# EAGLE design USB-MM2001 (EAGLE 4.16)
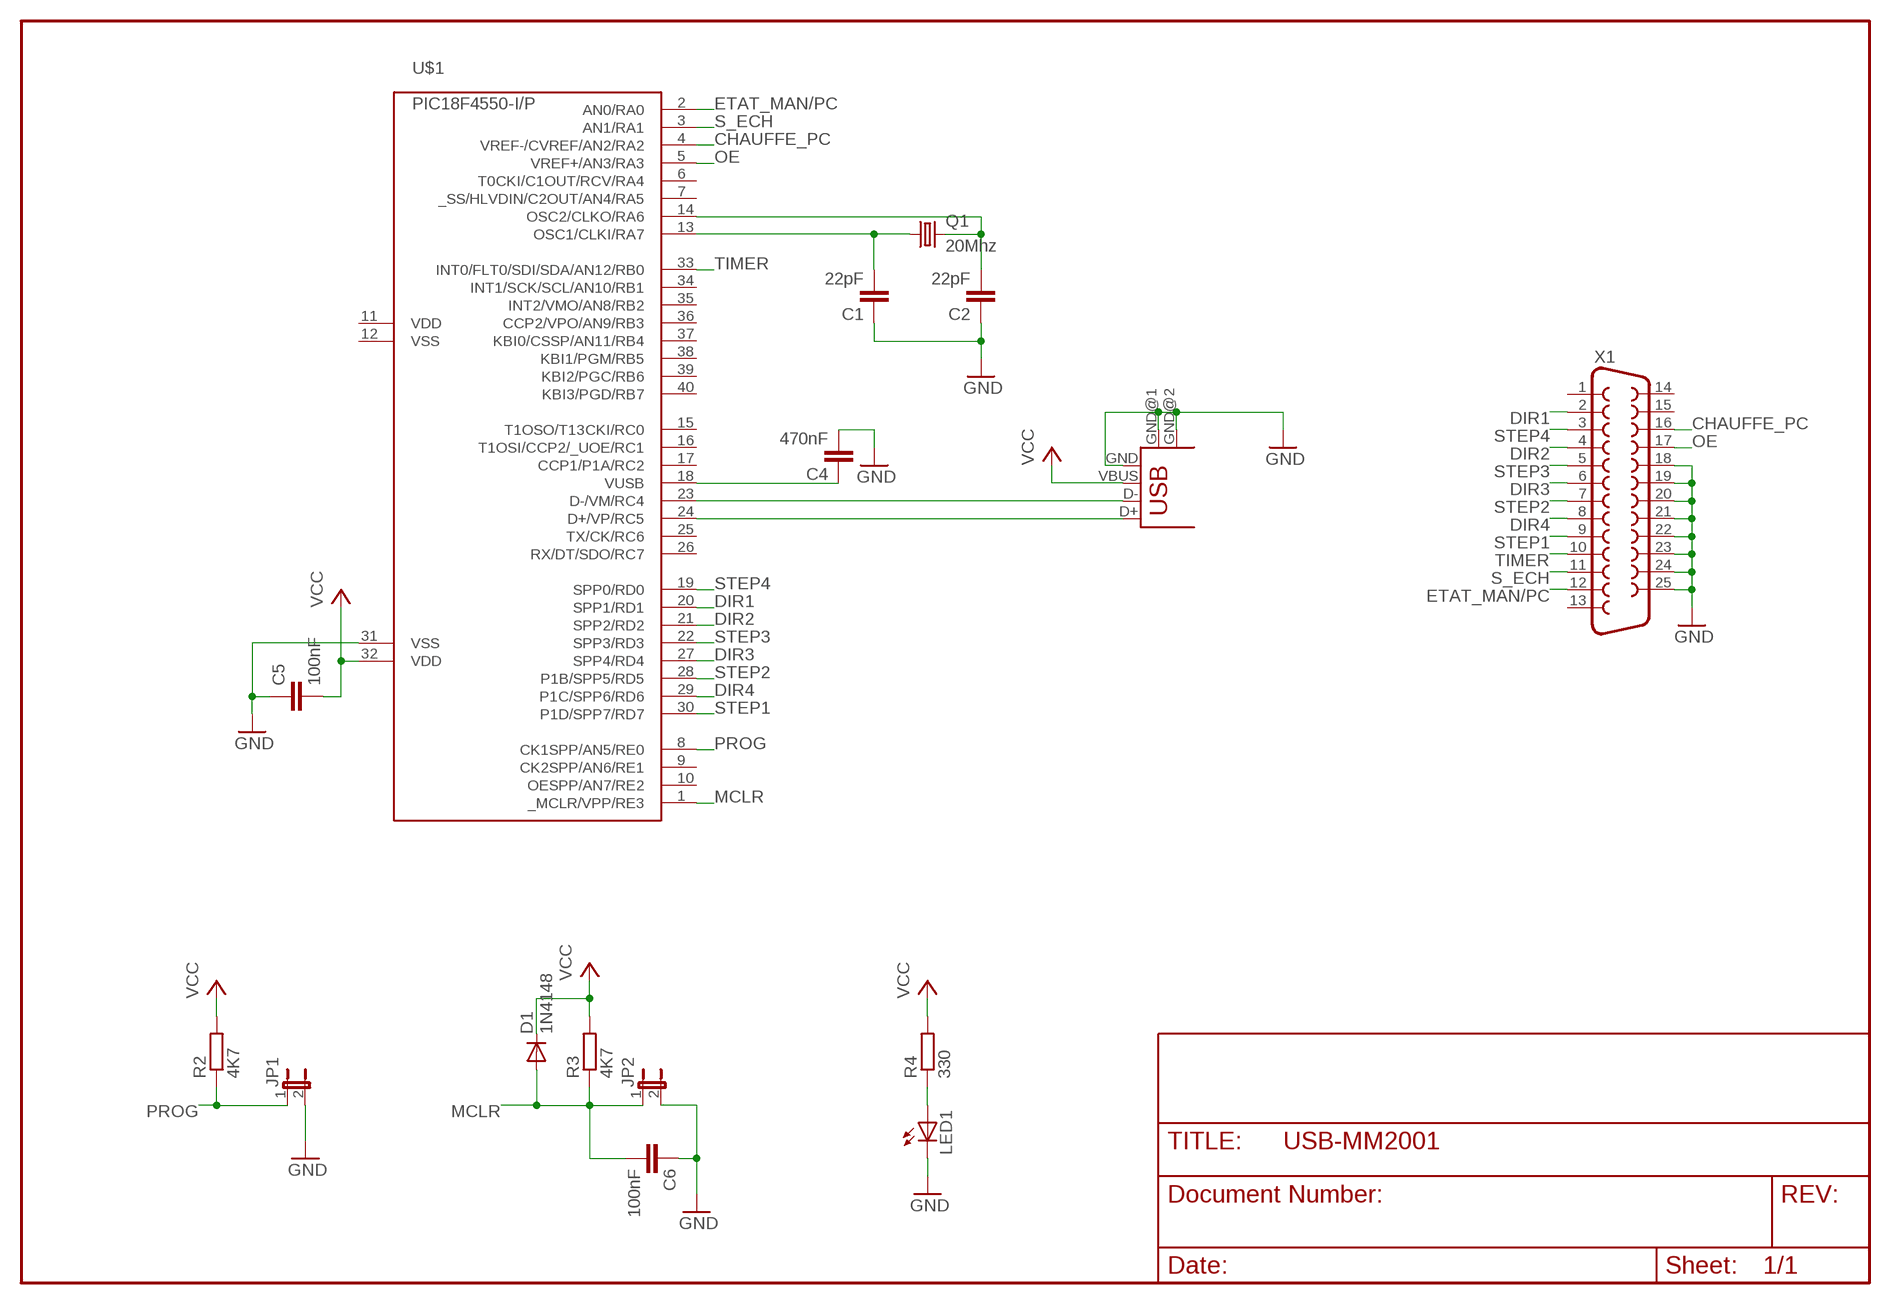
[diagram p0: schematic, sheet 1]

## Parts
C1  22pF  C-EU025-024X044  [C025-024X044]
C2  22pF  C-EU025-024X044  [C025-024X044]
C4  470nF  C-EU025-024X044  [C025-024X044]
C5  100nF  C-EU025-024X044  [C025-024X044]
C6  100nF  C-EU025-024X044  [C025-024X044]
D1  1N4148  [DO35-10]
JP1  JP1E  [JP1]
JP2  JP1E  [JP1]
LED1  LED5MM  [LED5MM]
Q1  20Mhz  CRYTALHC49U-V  [HC49U-V]
R2  4K7  R-EU_0207/10  [0207/10]
R3  4K7  R-EU_0207/10  [0207/10]
R4  330  R-EU_0207/10  [0207/10]
U$1  PIC18F4550-I/P  [DIL40]
USB1  USB-B-H  [USB-B-H]
X1  F25H  [F25H]

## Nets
CHAUFFE_PC: U$1.4(VREF-/CVREF/AN2/RA2) X1.16
DIR1: U$1.20(SPP1/RD1) X1.2
DIR2: U$1.21(SPP2/RD2) X1.4
DIR3: U$1.27(SPP4/RD4) X1.6
DIR4: U$1.29(P1C/SPP6/RD6) X1.8
ETAT_MAN/PC: U$1.2(AN0/RA0) X1.12
GND: C1.1 C2.1 C4.2 C5.1 C6.1 JP1.2 JP2.2 LED1.K(C) U$1.31(VSS) USB1.GND USB1.GND@1(GND) USB1.GND@2(GND) X1.18 X1.19 X1.20 X1.21 X1.22 X1.23 X1.24 X1.25
MCLR: C6.2 D1.A JP2.1 R3.1 U$1.1(_MCLR/VPP/RE3)
N$1: U$1.24(D+/VP/RC5) USB1.D+
N$2: U$1.23(D-/VM/RC4) USB1.D-
N$3: C4.1 U$1.18(VUSB)
N$7: LED1.A R4.1
N$11: C2.2 Q1.2 U$1.14(OSC2/CLKO/RA6)
N$14: C1.2 Q1.1 U$1.13(OSC1/CLKI/RA7)
OE: U$1.5(VREF+/AN3/RA3) X1.17
PROG: JP1.1 R2.1 U$1.8(CK1SPP/AN5/RE0)
S_ECH: U$1.3(AN1/RA1) X1.11
STEP1: U$1.30(P1D/SPP7/RD7) X1.9
STEP2: U$1.28(P1B/SPP5/RD5) X1.7
STEP3: U$1.22(SPP3/RD3) X1.5
STEP4: U$1.19(SPP0/RD0) X1.3
TIMER: U$1.33(INT0/FLT0/SDI/SDA/AN12/RB0) X1.10
VCC: C5.2 D1.C R2.2 R3.2 R4.2 U$1.32(VDD) USB1.VBUS
Unconnected: U$1.6(T0CKI/C1OUT/RCV/RA4) U$1.7(_SS/HLVDIN/C2OUT/AN4/RA5) U$1.9(CK2SPP/AN6/RE1) U$1.10(OESPP/AN7/RE2) U$1.15(T1OSO/T13CKI/RC0) U$1.16(T1OSI/CCP2/_UOE/RC1) U$1.17(CCP1/P1A/RC2) U$1.25(TX/CK/RC6) U$1.26(RX/DT/SDO/RC7) U$1.34(INT1/SCK/SCL/AN10/RB1) U$1.35(INT2/VMO/AN8/RB2) U$1.36(CCP2/VPO/AN9/RB3) U$1.37(KBI0/CSSP/AN11/RB4) U$1.38(KBI1/PGM/RB5) U$1.39(KBI2/PGC/RB6) U$1.40(KBI3/PGD/RB7) X1.1 X1.13 X1.14 X1.15

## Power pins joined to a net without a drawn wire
VDD: U$1.11(VDD)
VSS: U$1.12(VSS)

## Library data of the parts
C1 C2 C4-C6 = rcl:C-EU: CAPACITOR, European symbol
D1 = diode:1N4148: DIODE
JP1 JP2 = jumper:JP1E: JUMPER
LED1 = led:LED: LED
Q1 = crystal:CRYTAL: CRYSTAL
R2-R4 = rcl:R-EU_: RESISTOR, European symbol
U$1 = microchip-pic18fxx5x:PIC18*4550: PIC18*4550 Microchip FLASH Microcontroller with FS-USB DEVICE FEATURES FeaturePIC18*4550 Program Memory (bytes) 32k Program Memory (instructions) 16384 I/O Ports Ports A, B, C, D, E Capture/Compare/PWM Modules 1 Enhanced Capture/Compare/PWM Modules 1 Parallel Communications (PSP) Yes 10-bit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
USB1 = con-usb-2:USB: USB Connectors
X1 = con-subd:F25: SUB-D

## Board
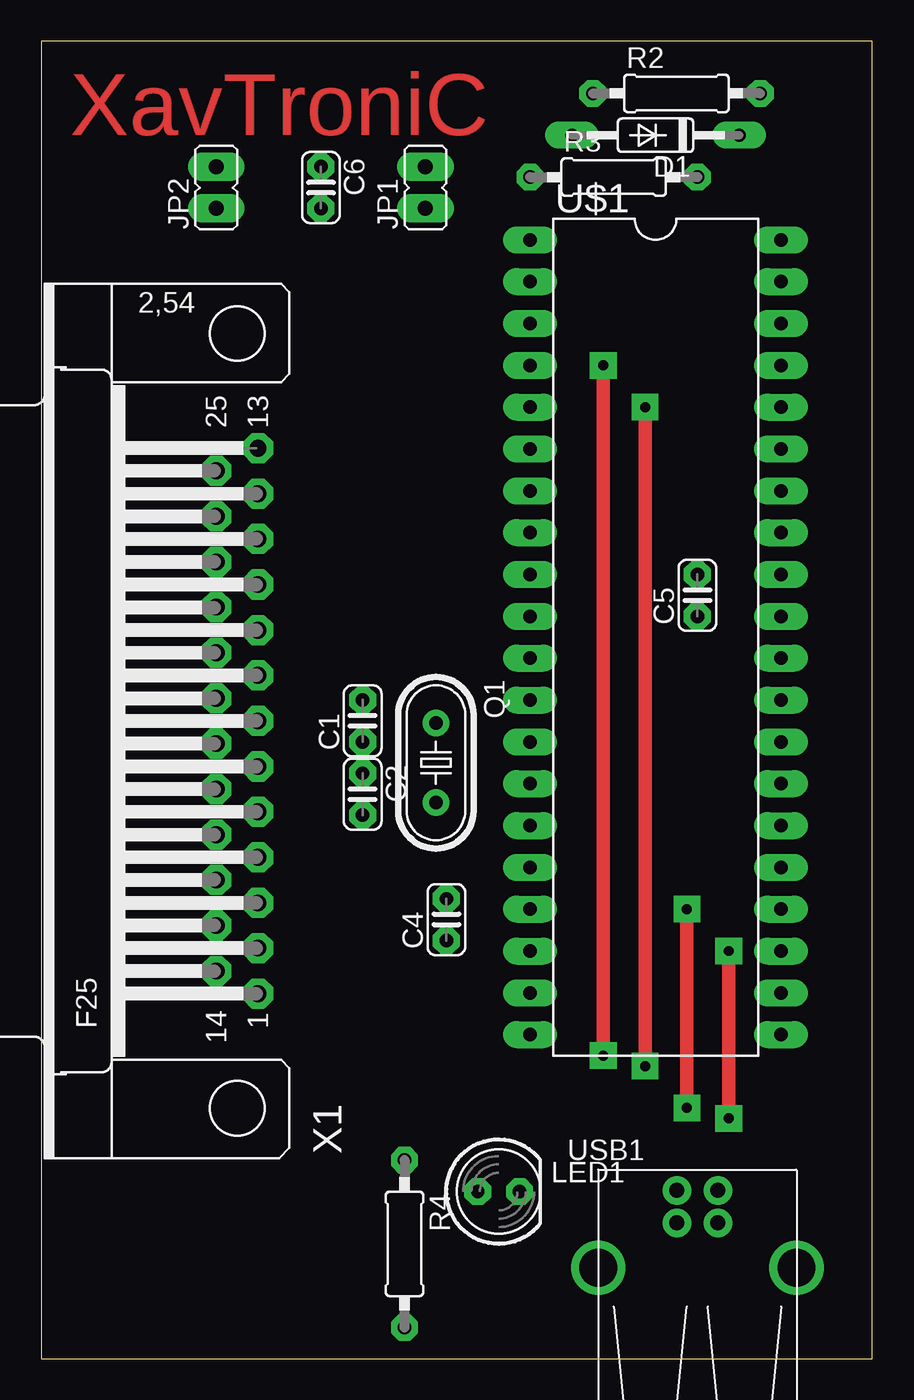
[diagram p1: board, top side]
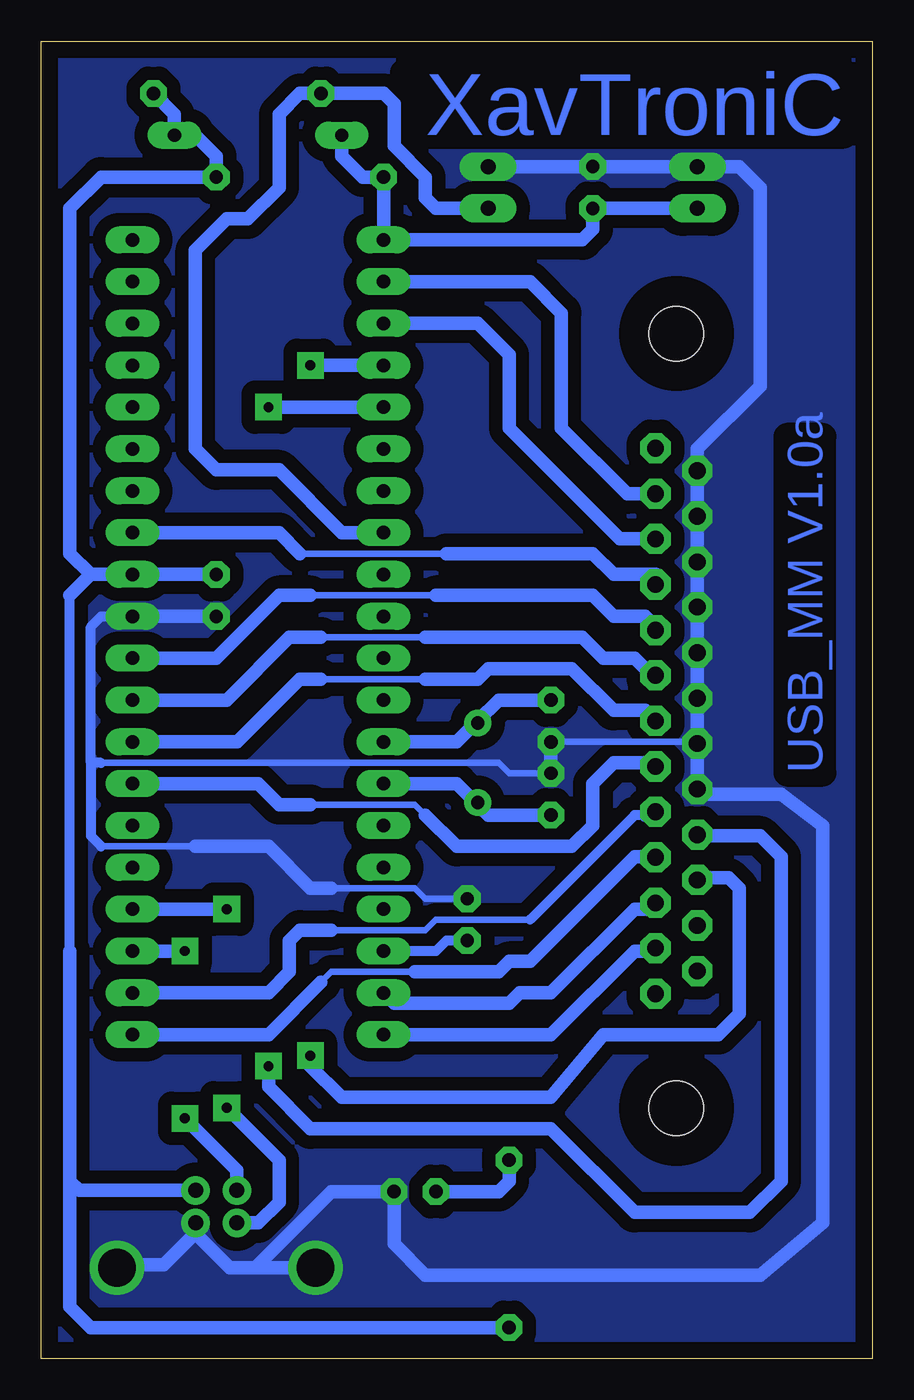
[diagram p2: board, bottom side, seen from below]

Size 50.47 x 80 mm. Coordinates in mm from the lower left corner, seen from the top.
Outline: 0,0 50.47,0 50.47,80 0,80 0,0
Copper layers (1*16): Top 0.035mm / dielectric 1.5mm / Bottom 0.035mm
Design rules "default": minimum track width 10mil, minimum drill 24mil, track to track 8mil, track to pad 8mil, pad to pad 8mil, via to via 8mil, smd to smd 8mil, copper to edge 40mil, drill to drill 8mil, minimum pad ring 16mil, minimum via ring 20mil, stop-mask expansion 4mil, vias tented up to drill 0mil, thermal gap 10mil

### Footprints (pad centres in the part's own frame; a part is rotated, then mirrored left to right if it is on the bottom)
C025-024X044 = drill 0.813 octagon: 1 -1.27,0; 2 1.27,0
DO35-10 = drill 0.813 long: A 5.08,0; C -5.08,0
JP1 = drill 0.914 long: 1 0,-1.27; 2 0,1.27
LED5MM = drill 0.813 octagon: A -1.27,0; K 1.27,0
HC49U-V = drill 0.813 round: 1 -2.413,0; 2 2.413,0
0207/10 = drill 0.813 octagon: 1 -5.08,0; 2 5.08,0
DIL40 = drill 0.813 long: 1 -24.13,-7.62; 2 -21.59,-7.62; 3 -19.05,-7.62; 4 -16.51,-7.62; 5 -13.97,-7.62; 6 -11.43,-7.62; 7 -8.89,-7.62; 8 -6.35,-7.62; 9 -3.81,-7.62; 10 -1.27,-7.62; 11 1.27,-7.62; 12 3.81,-7.62; 13 6.35,-7.62; 14 8.89,-7.62; 15 11.43,-7.62; 16 13.97,-7.62; 17 16.51,-7.62; 18 19.05,-7.62; 19 21.59,-7.62; 20 24.13,-7.62; 21 24.13,7.62; 22 21.59,7.62; 23 19.05,7.62; 24 16.51,7.62; 25 13.97,7.62; 26 11.43,7.62; 27 8.89,7.62; 28 6.35,7.62; 29 3.81,7.62; 30 1.27,7.62; 31 -1.27,7.62; 32 -3.81,7.62; 33 -6.35,7.62; 34 -8.89,7.62; 35 -11.43,7.62; 36 -13.97,7.62; 37 -16.51,7.62; 38 -19.05,7.62; 39 -21.59,7.62; 40 -24.13,7.62
USB-B-H = drill 0.914 round: D+ 0,1.25; D- 1.981,1.25; GND 0,-1.25; VBUS 1.981,-1.25 | drill 2.286 round: GND@1 -2.718,6.02; GND@2 -2.718,-6.02
F25H = drill 1.016 octagon: 1 -16.561,-1.27; 2 -13.792,-1.27; 3 -11.049,-1.27; 4 -8.28,-1.27; 5 -5.512,-1.27; 6 -2.769,-1.27; 7 0,-1.27; 8 2.769,-1.27; 9 5.512,-1.27; 10 8.28,-1.27; 11 11.049,-1.27; 12 13.792,-1.27; 13 16.561,-1.27; 14 -15.189,1.27; 15 -12.421,1.27; 16 -9.652,1.27; 17 -6.909,1.27; 18 -4.14,1.27; 19 -1.372,1.27; 20 1.372,1.27; 21 4.14,1.27; 22 6.909,1.27; 23 9.652,1.27; 24 12.421,1.27; 25 15.189,1.27 | hole 3.302: -23.52,0; 23.52,0

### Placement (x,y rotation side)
C1  19.52,38.73 90 top
C2  19.52,34.29 270 top
C4  24.6,26.66 90 top
C5  39.84,46.35 90 top
C6  16.98,71.11 270 top
D1  37.3,74.29 180 top
JP1  23.33,71.11 0 top
JP2  10.63,71.11 0 top
LED1  27.77,10.16 0 top
Q1  23.96,36.19 270 top
R2  38.57,76.83 0 top
R3  34.76,71.75 0 top
R4  22.06,6.98 270 top
U$1  37.3,43.81 270 top
USB1  39.84,8.25 90 top
X1  11.9,38.73 90 top

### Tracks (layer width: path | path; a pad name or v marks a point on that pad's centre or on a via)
CHAUFFE_PC  (via drill 0.6)
  Top 0.813: v34.12,18.41 v34.12,60.32
  Bottom 0.813: v34.12,60.32 U$1.4 | v34.12,18.41 34.12,17.77 32.22,15.87 19.52,15.87 16.34,19.68 9.36,19.68 8.09,20.95 8.09,28.57 8.73,29.2 10.63,29.2 X1.16
DIR1
  Bottom 0.813: U$1.20 19.52,19.68 14.44,24.76 13.17,24.76 X1.2
DIR2
  Bottom 0.406: 33.49,22.86 32.85,23.49 27.77,23.49
  Bottom 0.813: U$1.21 36.66,19.68 33.49,22.86 | 27.77,23.49 22.7,23.49 22.06,24.12 20.79,24.12 14.44,30.47 13.17,30.47 X1.4
DIR3
  Bottom 0.406: 34.12,33.65 27.77,33.65 27.14,33.02
  Bottom 0.813: U$1.27 37.3,34.92 36.03,33.65 34.12,33.65 | 27.14,33.02 25.23,31.11 18.25,31.11 16.98,32.38 16.98,34.92 15.71,36.19 13.17,36.19 X1.6
DIR4
  Bottom 0.406: 27.14,43.81 33.49,43.81
  Bottom 0.813: U$1.29 39.2,40 35.39,43.81 33.49,43.81 | 27.14,43.81 17.61,43.81 16.34,42.54 14.44,42.54 13.17,41.27 X1.8
ETAT_MAN/PC
  Bottom 0.813: X1.12 14.9,52.52 18.88,56.51 18.88,63.5 20.79,65.4 U$1.2
GND
  Bottom 0.406: 10.63,37.46 C1.1 | C4.2 27.14,27.93 27.77,28.57 32.85,28.57 | 46.82,31.11 41.11,31.11 | C2.1 22.06,35.55 22.7,36.19 46.82,36.19
  Bottom 0.61: 46.82,31.11 47.46,31.74 47.46,36.19 | 47.46,36.19 47.46,44.45 46.82,45.08 U$1.31 | 46.82,36.19 47.46,36.19
  Bottom 0.813: U$1.31 C5.1 | X1.20 10.63,40 | X1.20 X1.21 X1.22 X1.23 X1.24 X1.25 10.63,55.24 6.82,59.05 6.82,71.11 8.09,72.38 JP2.2 C6.1 JP1.2 | X1.20 10.63,37.46 X1.19 10.63,34.92 | C1.1 C2.1 | USB1.GND 41.09,7.63 41.11,7.62 | 41.11,7.62 43.02,5.71 45.55,5.71 45.73,5.53 USB1.GND@2 | 41.11,7.62 39.03,5.53 37.48,5.53 | 10.63,34.92 X1.18 | 10.63,34.92 10,34.29 5.55,34.29 3.01,32.38 3.01,8.25 6.82,5.08 27.14,5.08 29.04,6.98 LED1.K 32.85,10.16 37.48,5.53 | 33.67,5.53 USB1.GND@1 | 37.48,5.53 33.67,5.53 | 33.67,5.53 33.49,5.71 | 32.85,28.57 34.12,28.57 36.66,31.11 41.11,31.11
  pour Bottom (isolate 0.813, no thermals): -0.17,80 50.63,80 50.63,-0.01 -0.17,-0.01
MCLR
  Bottom 0.813: JP2.1 C6.2 16.98,68.57 17.61,67.94 U$1.1 R3.1 30.95,71.75 32.22,73.02 D1.A
N$1  (via drill 0.6)
  Top 0.813: v39.2,15.24 v39.2,27.3
  Bottom 0.813: USB1.D+ 37.3,8.25 36.03,9.52 36.03,12.06 v39.2,15.24 | v39.2,27.3 U$1.24
N$2  (via drill 0.6)
  Top 0.813: v41.74,14.6 v41.74,24.76
  Bottom 0.813: USB1.D- 38.59,11.45 v41.74,14.6 | v41.74,24.76 U$1.23
N$3
  Bottom 0.61: C4.1 25.87,25.39 26.5,24.76 U$1.18
N$7
  Bottom 0.813: R4.1 22.06,10.79 22.7,10.16 LED1.A
N$11
  Bottom 0.813: U$1.14 25.23,34.92 23.96,33.65 | 23.96,33.65 Q1.2 | C2.2 23.33,33.02 23.96,33.65
N$14
  Bottom 0.813: U$1.13 25.23,37.46 23.96,38.73 | 23.96,38.73 Q1.1 | C1.2 22.7,40 23.96,38.73
OE  (via drill 0.6)
  Top 0.813: v36.66,17.77 v36.66,57.78
  Bottom 0.813: v36.66,57.78 U$1.5 | v36.66,17.77 36.66,16.5 34.12,13.97 19.52,13.97 14.44,8.89 7.46,8.89 5.55,10.79 5.55,30.47 6.82,31.74 10.63,31.74 X1.17
PROG
  Bottom 0.813: U$1.8 32.22,50.16 36.03,53.97 39.84,53.97 41.11,55.24 41.11,67.3 39.2,69.21 37.94,69.21 36.03,71.11 36.03,75.56 34.76,76.83 R2.1 29.68,76.83 29.04,76.19 29.04,73.66 27.14,71.75 27.14,70.48 26.5,69.84 JP1.1
S_ECH
  Bottom 0.813: X1.11 15.33,49.78 22.06,56.51 22.06,60.96 23.96,62.86 U$1.3
STEP1
  Bottom 0.406: 26.5,46.35 34.12,46.35
  Bottom 0.813: U$1.30 39.84,42.54 36.03,46.35 34.12,46.35 | 26.5,46.35 16.98,46.35 15.71,45.08 13.81,45.08 13.17,44.45 X1.9
STEP2
  Bottom 0.406: 27.14,41.27 33.49,41.27
  Bottom 0.813: U$1.28 38.57,37.46 34.76,41.27 33.49,41.27 | 27.14,41.27 23.96,41.27 23.33,41.91 18.25,41.91 15.71,39.37 13.81,39.37 X1.7
STEP3
  Bottom 0.406: 20.79,26.66 26.5,26.66 27.14,26.03 32.85,26.03
  Bottom 0.61: 13.81,33.02 14.44,33.02 20.79,26.66
  Bottom 0.813: U$1.22 36.66,22.22 35.39,23.49 35.39,25.39 34.76,26.03 32.85,26.03 | X1.5 13.17,33.02 13.81,33.02
STEP4
  Bottom 0.813: X1.3 13.17,27.93 13.81,27.3 14.44,27.3 19.52,22.22 21.42,22.22 22.06,21.58 29.04,21.58 U$1.19
TIMER
  Bottom 0.406: 25.87,48.89 34.76,48.89
  Bottom 0.813: U$1.33 36.03,50.16 34.76,48.89 | 25.87,48.89 16.98,48.89 15.71,47.62 13.17,47.62 X1.10 13.17,46.98
VCC
  Bottom 0.61: 48.73,24.76 48.73,46.35
  Bottom 0.813: USB1.VBUS 48.17,10.23 48.73,10.79 | 47.46,47.62 48.73,46.35 | 47.46,47.62 U$1.32 C5.2 | R2.2 42.38,75.56 D1.C 41.11,74.29 39.84,73.02 R3.2 46.82,71.75 48.73,69.84 48.73,48.89 47.46,47.62 | 48.73,10.79 48.73,24.76 | R4.2 47.46,1.9 48.73,3.17 48.73,10.79

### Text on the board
Top: XavTroniC
Bottom: XavTroniC | USB_MM V1.0a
